// Mitsubishi GX Works2 project: 7.正反转   PLC: FX3U/FX3UC

PROGRAM MAIN
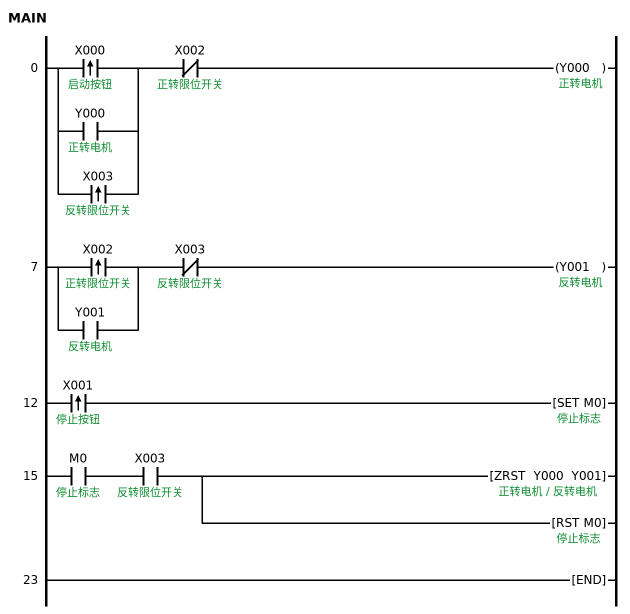
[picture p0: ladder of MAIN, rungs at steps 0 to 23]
0     LDP     X000  ; 启动按钮
      OR      Y000  ; 正转电机
      ORP     X003  ; 反转限位开关
      ANI     X002  ; 正转限位开关
      OUT     Y000  ; 正转电机
7     LDP     X002  ; 正转限位开关
      OR      Y001  ; 反转电机
      ANI     X003  ; 反转限位开关
      OUT     Y001  ; 反转电机
12    LDP     X001  ; 停止按钮
      SET     M0  ; 停止标志
15    LD      M0  ; 停止标志
      AND     X003  ; 反转限位开关
      ZRST    Y000 Y001
      RST     M0  ; 停止标志
23    END
END_PROGRAM
